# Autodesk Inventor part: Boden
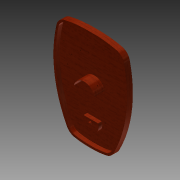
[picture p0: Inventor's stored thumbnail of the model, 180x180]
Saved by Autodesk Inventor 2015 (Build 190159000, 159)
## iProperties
Created: 2015-02
Part Number: Boden
Material: Holz (Eiche)
Document SubType Name: Modeling
Designer: Andreas
Density: 0.76 g/cm^3
Appearance: Weißeiche - natur - mittlerer Glanz
Author: Andreas
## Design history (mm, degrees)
sketch "Skizze3"
  geometry: A1 r 140 centre (-2.816, 139.972) between (-30.657, 2.768) and (0, 0); A2 r 20 centre (-26.68, 22.368) between (-44.441, 13.175) and (-30.657, 2.768); A3 r 232.064 centre (161.65, 119.852) between (-64.479, 172) and (-44.441, 13.175); A4 r 20 centre (-44.99, 167.506) between (-49.459, 187) and (-64.479, 172); A5 r 200 centre (-4.769, -7.943) between (0, 192) and (-49.459, 187); A6 r 140 centre (2.816, 139.972) between (0, 0) and (30.657, 2.768); A7 r 20 centre (26.68, 22.368) between (30.657, 2.768) and (44.441, 13.175); A8 r 232.064 centre (-161.65, 119.852) between (44.441, 13.175) and (64.479, 172); A9 r 20 centre (44.99, 167.506) between (64.479, 172) and (49.459, 187); A10 r 200 centre (4.769, -7.943) between (49.459, 187) and (0, 192); 1 further point
  constraints: 20 point on circle, 10 centre point, 2 tangent
extrude "Extrusion1" new body sketch "Skizze3" distance "d0" = 3; taper "d1" = 0 deg
sketch "Skizze4"
  geometry: A1 r 140 centre (-2.816, 139.972) between (-30.657, 2.768) and (0, 0); A2 r 20 centre (-26.68, 22.368) between (-44.441, 13.175) and (-30.657, 2.768); A3 r 232.064 centre (161.65, 119.852) between (-64.479, 172) and (-44.441, 13.175); A4 r 20 centre (-44.99, 167.506) between (-49.459, 187) and (-64.479, 172); A5 r 200 centre (-4.769, -7.943) between (0, 192) and (-49.459, 187); A6 r 200 centre (4.769, -7.943) between (49.459, 187) and (0, 192); A7 r 20 centre (44.99, 167.506) between (64.479, 172) and (49.459, 187); A8 r 232.064 centre (-161.65, 119.852) between (44.441, 13.175) and (64.479, 172); A9 r 20 centre (26.68, 22.368) between (30.657, 2.768) and (44.441, 13.175); A10 r 140 centre (2.816, 139.972) between (0, 0) and (30.657, 2.768); A11 r 16 centre (-26.68, 22.368) between (-40.889, 15.013) and (-29.862, 6.688); A12 r 136 centre (-2.816, 139.972) between (-29.862, 6.688) and (0, 4.001); A13 r 136 centre (2.816, 139.972) between (0, 4.001) and (29.862, 6.688); A14 r 16 centre (26.68, 22.368) between (29.862, 6.688) and (40.889, 15.013); A15 r 228.064 centre (-161.65, 119.852) between (40.889, 15.013) and (60.581, 171.101); A16 r 16 centre (44.99, 167.506) between (60.581, 171.101) and (48.565, 183.101); A17 r 196 centre (4.769, -7.943) between (48.565, 183.101) and (0, 187.999); A18 r 196 centre (-4.769, -7.943) between (0, 187.999) and (-48.565, 183.101); A19 r 16 centre (-44.99, 167.506) between (-48.565, 183.101) and (-60.581, 171.101); A20 r 228.064 centre (161.65, 119.852) between (-60.581, 171.101) and (-40.889, 15.013)
  constraints: 40 point on circle, 20 centre point, 1 tangent, 9 other
  dimensions: "d2" = 4 radial gap between concentric circles of A3 A20
extrude "Extrusion2" join sketch "Skizze4" distance "d3" = 8; taper "d4" = 0 deg
sketch "Skizze5"
  geometry: L1 (-19.106, 99.9)-(-19.596, 100); L2 (19.106, 99.9)-(19.596, 100); A1 r 20 centre (0, 96) between (19.596, 100) and (-19.596, 100); A2 r 19.5 centre (0, 96) between (19.106, 99.9) and (-19.106, 99.9); 2 further points
  constraints: 4 end point, 4 point on circle, 2 centre point, 1 coincident
  dimensions: "d6" = 40 diameter of A1; "d7" = 0.5 radial gap between concentric circles of A1 A2
extrude "Extrusion3" join sketch "Skizze5" distance "d8" = 20; taper "d9" = 0 deg
sketch "Skizze6"
  geometry: L1 (-13.748, 47)-(13.748, 47); A1 r 15 centre (0, 41) between (-13.748, 47) and (13.748, 47); 2 further points
  constraints: 2 end point, 2 point on circle, 1 centre point, 1 coincident, 1 horizontal
  dimensions: "d11" = 30 diameter of A1
extrude "Extrusion4" join sketch "Skizze6" distance "d12" = 7; taper "d13" = 0 deg
sketch "Skizze7"
  geometry: C1 r 2.5 at (0, 41); A1 r 15 centre (0, 41) between (-13.748, 47) and (13.748, 47) reference; 1 further point
  constraints: 1 centre point, 1 coincident
  dimensions: "d14" = 5 diameter of C1
extrude "Extrusion5" join sketch "Skizze7" distance "d15" = 3; taper "d16" = 0 deg
chamfer "Fase1" distance "d17" = 1; stored, may be unused: second distance "d18" = 2, angle "d19" = 45 deg
node "Volumenkörper1"
